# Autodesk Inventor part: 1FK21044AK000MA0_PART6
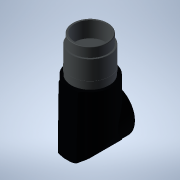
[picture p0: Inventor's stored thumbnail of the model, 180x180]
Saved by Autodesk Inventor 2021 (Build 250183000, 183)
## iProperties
Created: 2025-04
Part Number: 1FK21044AK000MA0_PART6
Material: Generic
Catalog Web Link: www.3dfindit.com
Description: -Servo synchronous motor
Document SubType Name: Modeling
Designer: psAdmin
Mass: 11.0817 g
Surface Area: 35.706 cm^2
Volume: 11.0817 cm^3
Density: 1 g/cm^3
Appearance: PSOLRGB-176-176-176
Category: PARTsolutions
Title: 1FK21044AK000MA0_PART6
Author: Cadenas PARTsolutions
Comments: Servo synchronous motor
Sending System: PARTsolutions
Preprocessor: ST-DEVELOPER v19.3
PSOL_IDENT_0: {$CADENAS_DATA/23d-libs/siemens_ag/_cat_/87/f4/1fk21044ak000ma0.prj},213 {VTYP=3D},{NB=1FK21044AK000
PSOL_IDENT_1: MA0_PART6},{LINA=1FK21044AK000MA0_PART6},{NN=1FK21044AK000MA0_PART6},{NOPRJ=TRUE},{DATE=19.08.2025 1
PSOL_IDENT_2: 4:00:48},{GEOMDATE=30.07.2025 02:00:50},{VERSION=},{LINEID=10},{WBVAR=},{WBNUMERIC=}  {NB=1FK21044AK
PSOL_IDENT_3: 000MA0_PART6},{LINA=1FK21044AK000MA0_PART6},{KT=DUMMY},{PREVIEW=../../../_pool_/cb/72/p_d211_xx_0043
PSOL_IDENT_4: 4j.png},{DESCSHORT=SIMOTICS S-1FK2 HD, SINAMICS S210 3AC 400V-480V, 0.95 Nm, 6000 rpm},{DESCLONG=SIM
PSOL_IDENT_5: OTICS S-1FK2 HD servo motor M0=1.27 Nm; PN = 0.6 kW at nN=6000 rpm (380-480 V); PN = 0.4 kW at nN=30
PSOL_IDENT_6: 00 rpm (200-240 V); degree of protection IP64; cylindrical shaft D19x40mm; absolute encoder 22-bit +
PSOL_IDENT_7: 12-bit multiturn (encoder AM22DQC); with OCC interface; plug size M17, rotatable; SIMOTICS S-1FK2 s
PSOL_IDENT_8: ervomotorfor a wide range of uses in industrial environments. SIMOTICS S‑1FK2 servomotors are compac
PSOL_IDENT_9: t synchronous motors with a high dynamic performance that set themselves apart as a result of their
PSOL_IDENT_10: high power density, degree of protection and overload capability. The motors are available in two va
PSOL_IDENT_11: riants: as High Dynamic variant (highest dynamic performance as a result of the low intrinsic moment
PSOL_IDENT_12: of inertia for applications demanding a high dynamic performance with low moved masses) - and as Co
PSOL_IDENT_13: mpact variant (precise and stable closed-loop control for medium up to large moved masses as a resul
PSOL_IDENT_14: t of a medium intrinsic moment of inertia). SIMOTICSS‑1FK2 servomotors fully exploit their strengths
PSOL_IDENT_15: in a system with the SINAMICSS210 frequency converter and simple connection using the one cable con
PSOL_IDENT_16: nection (OCC). Advantages include the short control and positioning times, fast and precise correcti
PSOL_IDENT_17: on of disturbing quantities as well as stable control with a high dynamic performance. The servo mot
PSOL_IDENT_18: ors can be configured to address a wide range of requirements. For example with and without holding
PSOL_IDENT_19: brake, IP64 or IP65 degree of protection, singleturn or multiturn absolute encoders - to name just a
PSOL_IDENT_20: few. Further, the servomotors are available in different shaft heights extending from 20 to 100. A
PSOL_IDENT_21: shaft sealing ring is available to achieve an IP65 degree of protection and for subsequent mounting
PSOL_IDENT_22: at the motor or as spare part. SIMOTICS - the optimum motor for each and every motion control applic
PSOL_IDENT_23: ation.},{INTNO=195125056312},{SUPPLIERALTNO=1FK2104-4AK00-0MA0},{MANUID=1FK21044AK000MA0},{MANUNAME=
PSOL_IDENT_24: Siemens},{MANUTYPEDESC=Synchronous motor 1FK2-HD 1,27 Nm},{AAU732=SIMOTICS},{AAO057=S-1FK2},{AAU734=
PSOL_IDENT_25: SIMOTICS S-1FK2 HD servo motor M0=1.27 Nm; PN = 0.6 kW at nN=6000 rpm (380-480 V); PN = 0.4 kW at nN=
PSOL_IDENT_26: 3000 rpm (200-240 V); degree of protection IP64; cylindrical shaft D19x40mm; absolute encoder 22-bit
PSOL_IDENT_27: + 12-bit multiturn (encoder AM22DQC); with OCC interface; plug size M17, rotatable;},{AAW338=Synchr
PSOL_IDENT_28: onous motor 1FK2-HD 1,27 Nm},{AAO742=SIMOTICS},{AAO663=4042948690994},{NOCUPEROU=1},{PRICEQUANTITY=1
PSOL_IDENT_29: },{QUANTITYMIN=1},{QUANTITYINT=1},{CTN=85015100},{COO=DE},{AAO676=1FK2104-4AK00-0MA0},{AAO677=Siemen
PSOL_IDENT_30: s AG},{ORDERUNIT=C62},{CONTENTUNIT=C62}
NB: 1FK21044AK000MA0_PART6
NT: Servo synchronous motor
NBSYN: $MANUID._PART6
LINA: 1FK21044AK000MA0_PART6
CATALOG: SIEMENS
PREVIEW: ../../../_pool_/cb/72/p_d211_xx_00434j.png
DESCSHORT: SIMOTICS S-1FK2 HD, SINAMICS S210 3AC 400V-480V, 0.95 Nm, 6000 rpm
DESCLONG: SIMOTICS S-1FK2 HD servo motor M0=1.27 Nm; PN = 0.6 kW at nN=6000 rpm (380-480 V); PN = 0.4 kW at nN=3000 rpm (200-240 V); degree of protection IP64; cylindrica
INTNO: 195125056312
SUPPLIERALTNO: 1FK2104-4AK00-0MA0
MANUID: 1FK21044AK000MA0
MANUNAME: Siemens
MANUTYPEDESC: Synchronous motor 1FK2-HD 1,27 Nm
AAU732: SIMOTICS
AAO057: S-1FK2
AAU734: SIMOTICS S-1FK2 HD servo motor M0=1.27 Nm; PN = 0.6 kW at nN=6000 rpm (380-480 V); PN = 0.4 kW at nN=3000 rpm (200-240 V); degree of protection IP64; cylindrica
AAW338: Synchronous motor 1FK2-HD 1,27 Nm
AAO742: SIMOTICS
AAO663: 4042948690994.0
NOCUPEROU: 1
PRICEQUANTITY: 1
QUANTITYMIN: 1
QUANTITYINT: 1
CTN: 85015100
COO: DE
ARTICLENO: 1FK21044AK000MA0_PART6
BOMINFO: 1FK21044AK000MA0_PART6
CREATOR: CADENAS GmbH
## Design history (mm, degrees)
feature "2025_04_17_15_37_40_0556"
body "Solid1"
